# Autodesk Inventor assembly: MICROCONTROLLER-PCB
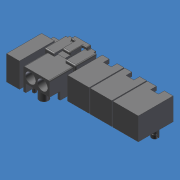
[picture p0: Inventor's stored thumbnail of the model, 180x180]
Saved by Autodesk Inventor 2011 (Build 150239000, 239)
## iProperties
Created: 2007-09
Part Number: MICROCONTROLLER-PCB
Document SubType Name: Assembly
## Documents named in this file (5)
- C:\Data Folder\VEX 2011\Inventor Datasets\Unit 16\Components\MICROCONTROLLER-PCB.iam
- C:\Data Folder\VEX 2011\Inventor Datasets\Unit 16\Components\MICROCONTROLLER-PCB-PIN4.ipt
- C:\Data Folder\VEX 2011\Inventor Datasets\Unit 16\Components\MICROCONTROLLER-PCB-PIN6.ipt
- C:\Data Folder\VEX 2011\Inventor Datasets\Unit 16\Components\MICROCONTROLLER-PCB-POWER.ipt
- C:\Data Folder\VEX 2011\Inventor Datasets\Unit 16\Components\MICROCONTROLLER-PCB-SWITCH.ipt
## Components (5 placed, 4 different names)
1. MICROCONTROLLER-PCB-PIN4
2. MICROCONTROLLER-PCB-PIN6
3. MICROCONTROLLER-PCB-POWER
4. MICROCONTROLLER-PCB-PIN4
5. MICROCONTROLLER-PCB-SWITCH
